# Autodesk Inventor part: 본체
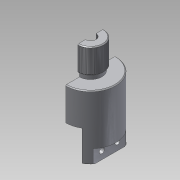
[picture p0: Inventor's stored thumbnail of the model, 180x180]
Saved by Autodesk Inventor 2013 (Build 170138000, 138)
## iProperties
Created: 2019-02
Part Number: 본체
Material: 알루미늄 6061
Document SubType Name: Modeling
Designer: Administrator
Density: 2.71 g/cm^3
Mass: 345.756 g
Surface Area: 298.528 cm^2
Volume: 127.585 cm^3
Author: Administrator
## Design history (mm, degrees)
sketch "스케치1"
  geometry: C1 r 29 at (0, 0); 1 further point
  constraints: 1 centre point, 1 coincident
  dimensions: "d0" = 58 diameter of C1
extrude "돌출1" new body sketch "스케치1" distance "d1" = 38; taper "d3" = 0 deg; dims "d2" = 36, "d4" = 0
sketch "스케치2"
  geometry: C1 r 13 at (0, 0); 1 further point
  constraints: 1 centre point, 1 coincident
  dimensions: "d5" = 26 diameter of C1
extrude "돌출2" join sketch "스케치2" distance "d6" = 5; taper "d7" = 0 deg
sketch "스케치3"
  geometry: C1 r 13 at (0, 0) reference; C2 r 15 at (0, 0)
  constraints: 1 centre point, 1 coincident
  dimensions: "d9" = 30 diameter of C2
extrude "돌출3" join sketch "스케치3" distance "d10" = 29; taper "d11" = 0 deg
hole "구멍1" diameter "d14" = 12.376; stored, may be unused: countersink angle "d18" = 90 deg, drill point angle "d20" = 118 deg; dims "d15" = 18, "d16" = 4, "d17" = 2, "d19" = 22, "d107" = 10, "d108" = 10
feature "스레드1" dims "d21" = 10, "d22" = 0
chamfer "모따기1" distance "d23" = 1; stored, may be unused: second distance "d24" = 2, angle "d25" = 45 deg
sketch "스케치5"
  geometry: L1 (-15, 0)-(15, 0); L2 (15, 0)-(15, -36); L3 (15, -36)-(-15, -36); L4 (-15, -36)-(-15, 0); L5 (-29, -36)-(29, -36) reference; L6 (-29, -20)-(-22, -20); L7 (-22, -20)-(-22, -36); L8 (-22, -36)-(-29, -36); L9 (-29, -36)-(-29, -20); L10 (29, -20)-(22, -20); L11 (22, -20)-(22, -36); L12 (22, -36)-(29, -36); L13 (29, -36)-(29, -20); L14 (-29, -36)-(-29, 38) reference; L15 (-29, -36)-(29, -36) reference; L16 (29, 38)-(-29, 38) reference; L17 (29, -36)-(29, 38) reference; 2 further points
  constraints: 24 end point, 6 parallel, 3 horizontal, 3 perpendicular, 2 collinear, 2 equal length, 2 midpoint, 2 point on line
  dimensions: "d31" = 36 distance of L3.end L1.start; "d33" = 30 distance of L2.end L3.end; "d36" = 16 distance of L12.end L10.start; "d37" = 44 distance between parallel lines of L11 L7
extrude "돌출5" cut sketch "스케치5" stored distance "d34" = 29; taper "d35" = 0 deg
sketch "스케치6"
  geometry: L1 (0, 0)-(0, 37.789) reference; 3 further points
  constraints: 1 vertical alignment
  dimensions: "d38" = 18 distance of point (9, 9.894) point (9, 27.894); "d40" = 9 distance from line of point (9, 9.894) L1; "d41" = 9 vertical distance of point (36, 18.894) point (9, 27.894)
hole "구멍2" sketch "스케치6" at (9, 27.894), (9, 9.894) diameter "d42" = 6; stored, may be unused: countersink angle "d46" = 90 deg, drill point angle "d48" = 118 deg; dims "d43" = 18, "d44" = 4, "d45" = 2, "d47" = 22
chamfer "모따기2" distance "d49" = 1; stored, may be unused: second distance "d50" = 2, angle "d51" = 45 deg
sketch "스케치7"
  geometry: C1 r 14 at (0, 0); A1 r 29 centre (0, 0) between (15, 24.819) and (-15, 24.819) reference
  constraints: 1 centre point, 1 coincident
  dimensions: "d68" = 28 diameter of C1
extrude "돌출6" cut sketch "스케치7" distance "d53" = 20; taper "d54" = 0 deg
sketch "스케치10"
  geometry: C1 r 4 at (0, 0) reference; C2 r 14 at (0, 0) reference; C3 r 16 at (0, 0)
  constraints: 1 centre point, 1 coincident
  dimensions: "d70" = 32 diameter of C3
extrude "돌출8" cut sketch "스케치10" distance "d72" = 7; taper "d73" = 0 deg
sketch "스케치12"
  geometry: C1 r 4 at (0, 0) reference
extrude "돌출9" cut sketch "스케치12" stored distance "d82" = 7; taper "d83" = 0 deg
sketch "스케치15"
  geometry: L1 (-17, 2.65)-(-14, 2.65); L2 (-14, 2.65)-(-14, 7.35); L3 (-14, 7.35)-(-17, 7.35); L4 (-17, 7.35)-(-17, 2.65); L5 (-17, 11.65)-(-14, 11.65); L6 (-14, 11.65)-(-14, 16.35); L7 (-14, 16.35)-(-17, 16.35); L8 (-17, 16.35)-(-17, 11.65); L9 (-14, 0)-(-14, 20) reference; L10 (24.819, 0)-(-24.819, 0) reference; L11 (0, 0)-(0, 11.65); L12 (14, 0)-(14, 20) reference; 2 further points
  constraints: 18 end point, 4 parallel, 3 perpendicular, 2 collinear, 2 equal length, 2 horizontal, 2 midpoint
  dimensions: "d102" = 5 distance from line of point (-17, 5) L10; "d103" = 9 distance of point (-17, 14) point (-17, 5); "d104" = 4.7 distance of L1.end L2.end; "d105" = 3 distance of L1.start L1.end
revolve "회전3" sketch "스케치15" stored, may be unused: angle "d106" = 90 deg
fillet "모깎기2" dims "d84" = 0.8
chamfer "모따기4" distance "d85" = 1; stored, may be unused: second distance "d86" = 2, angle "d87" = 45 deg
node "작업 평면1"
sketch "스케치13"
  geometry: L1 (-5, 33)-(5, 33); L2 (5, 33)-(5, -7); L3 (5, -7)-(-5, -7); L4 (-5, -7)-(-5, 33); L5 (29, 38)-(-29, 38) reference; 2 further points
  constraints: 8 end point, 2 parallel, 1 horizontal, 1 midpoint, 1 perpendicular, 1 vertical alignment
  dimensions: "d89" = 40 distance of L1.end L2.end; "d91" = 10 distance of L1.start L1.end; "d92" = 5 distance between parallel lines of L1 L5
extrude "돌출10" join sketch "스케치13" stored distance "d93" = 7; taper "d94" = 0 deg
sketch "스케치14"
  geometry: L1 (-7, 5)-(-7, -5) reference; L2 (-7, -5)-(33, -5) reference; 2 further points
  constraints: 1 other
  dimensions: "d95" = 20 distance from line of point (13, 0) L1; "d96" = 5 distance from line of point (13, 0) L2
feature "엠보싱1" sketch "스케치14" dims "d97" = 0.5, "d98" = 0
chamfer "모따기5" distance "d99" = 1; stored, may be unused: second distance "d100" = 2, angle "d101" = 45 deg
node "솔리드1"
node "투영된 루프1"
